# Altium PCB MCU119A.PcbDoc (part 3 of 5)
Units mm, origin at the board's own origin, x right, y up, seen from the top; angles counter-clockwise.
Board outline 58.62 x 144.37 mm, 6 copper layers (Top Signal, GND, Middle Signal, PWR, GND2, Bottom Signal), stack 1.566 mm thick; 316 components, 238 nets, 1210 pads, 1064 vias.
Unrouted connection lines stored in the file: 59.
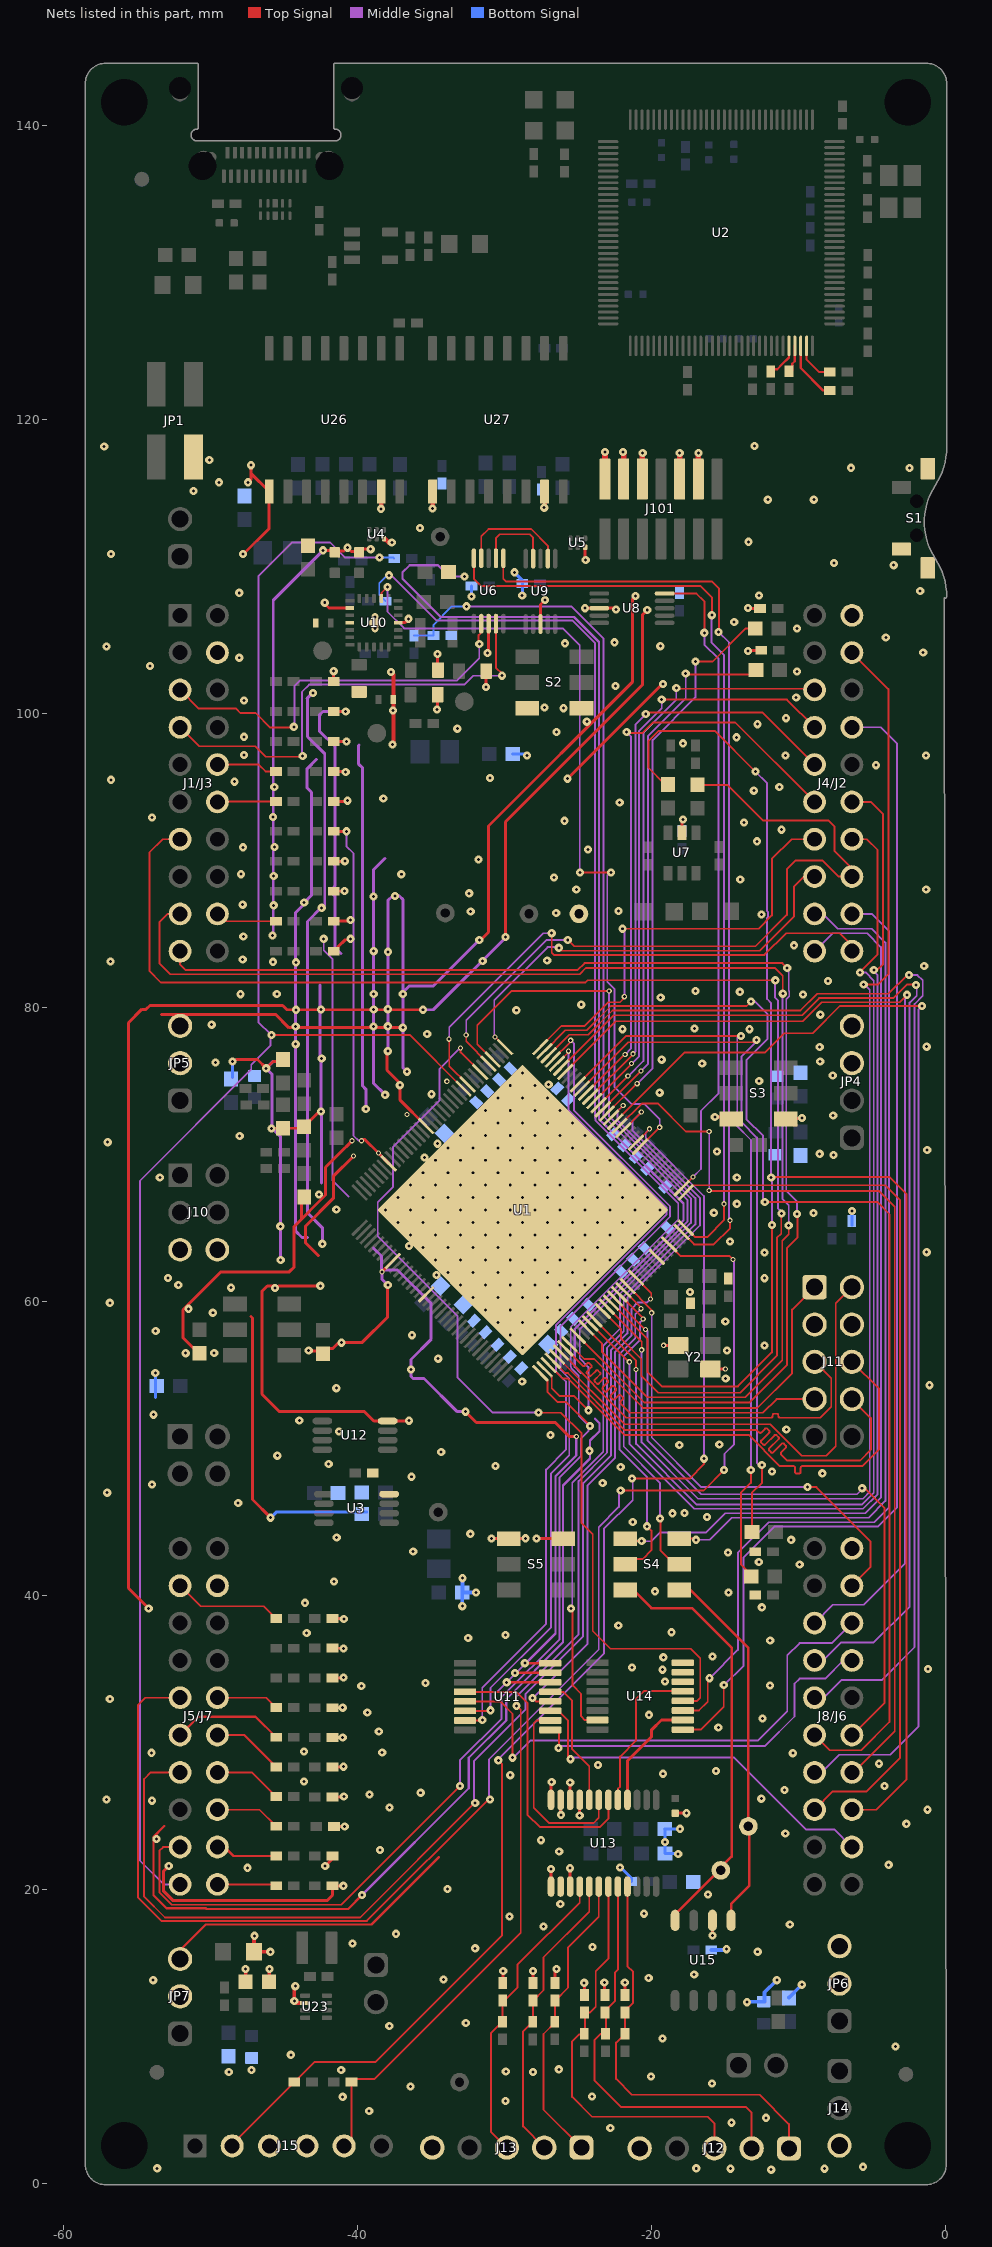
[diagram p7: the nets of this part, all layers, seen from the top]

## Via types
v1: diameter 0.559, hole 0.203, Top Signal to Bottom Signal, tented both sides, 833 vias
v2: diameter 0.5, hole 0.2, Top Signal to Bottom Signal, tented both sides, 146 vias
v3: diameter 0.356, hole 0.203, Top Signal to Bottom Signal, tented both sides, 83 vias
v4: diameter 0.4, hole 0.2, Top Signal to Bottom Signal, tented both sides, 2 vias

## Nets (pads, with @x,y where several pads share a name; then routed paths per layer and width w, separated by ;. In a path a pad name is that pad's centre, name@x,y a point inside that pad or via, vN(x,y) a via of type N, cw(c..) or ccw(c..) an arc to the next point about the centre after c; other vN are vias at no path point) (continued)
ADCINB9: J5/J7.67 R51.1 | length 4.7
  Top Signal w0.127: J5/J7.67@-49.521,27.96 -47.175,27.96 R51.1@-45.523,26.308
ADCINC0: J5/J7.68 R52.1 | length 4.5
  Top Signal w0.127: J5/J7.68@-49.521,25.42 -46.655,25.42 R52.1@-45.523,24.288
ADCINC1: J1/J3.29 R53.1 | length 4.2
  Top Signal w0.127: J1/J3.29@-49.521,86.38 -49.024,85.883 R53.1@-45.534,85.883
ADCINC2: J5/J7.42 R54.1 | length 7.5
  Top Signal w0.127: J5/J7.42@-52.061,40.66 -50.669,39.268 -46.362,39.268 R54.1@-45.523,38.43
ADCINC3: J5/J7.46 R55.1 | length 7.6
  Top Signal w0.152: J5/J7.46@-52.061,30.5 -50.811,31.75 -46.925,31.75 R55.1@-45.523,30.349
ADCINC8: J5/J7.66 R56.1 | length 4.9
  Top Signal w0.152: J5/J7.66@-49.521,30.5 -47.695,30.5 R56.1@-45.523,28.329
ADCIND1: J1/J3.25 R57.1 | length 4.2
  Top Signal w0.127: J1/J3.25@-49.521,96.54 -46.713,96.54 -46.248,96.075 R57.1@-45.534,96.075
ADCIND5: J5/J7.65 R58.1 | length 4.3
  Top Signal w0.127: J5/J7.65@-49.521,33.04 -46.194,33.04 R58.1@-45.523,32.369
ADCINE0/DACB_OUT: J5/J7.70 R60.1 | length 4
  Top Signal w0.127: J5/J7.70@-49.521,20.34 -45.616,20.34 R60.1@-45.523,20.247
ADCINE1: J5/J7.69 R61.1 | length 4.3
  Top Signal w0.152: J5/J7.69@-49.521,22.88 -49.042,22.88 -48.43,22.268 R61.1@-45.523,22.268
ADCINE7: J1/J3.26 R62.1 | length 4
  Top Signal w0.127: J1/J3.26@-49.521,94 -49.484,94.037 R62.1@-45.534,94.037
DEBUG_ID4: R101.1 U2.63 | length 2.9
  Top Signal w0.127: -9.426,124.102 -8.588,123.263 R101.1@-7.851,123.263
  Top Signal w0.152: -9.426,124.102 U2.63@-9.426,125.035
DEBUG_ID5: R102.1 U2.62 | length 4.1
  Top Signal w0.152: U2.62@-9.826,125.035 -9.826,123.522 -8.303,122 R102.1@-7.851,122
DEBUG_ID6: R103.1 U2.61 | length 2
  Top Signal w0.152: R103.1@-10.604,123.162 -10.405,123.362 -10.405,123.811 -10.235,123.981 -10.235,125.026 U2.61@-10.226,125.035
DEBUG_ID7: R104.1 U2.60 | length 2.5
  Top Signal w0.152: R104.1@-11.852,123.143 -11.852,123.232 -11.639,123.445 -11.424,123.445 -11.093,123.776 -10.626,124.243 U2.60@-10.626,125.035
EQEP1A: C6.1 J12.1 R5.1 U13.21 | length 28.4
  Top Signal w0.127: C6.1@-21.793,11.617 -21.793,11.735 -21.234,12.294 -21.234,14.376 -21.616,14.758 U13.21@-21.616,20.189 ; C6.1@-21.784,11.601 R5.1@-21.784,10.179 -22.389,9.574 -22.389,7.098 -21.311,6.02 -12.624,6.02 -10.624,4.02 J12.1@-10.624,2.368
EQEP1B: C7.1 J12.2 R6.1 U13.20 | length 28.1
  Top Signal w0.127: C7.1@-23.165,11.567 -23.089,11.49 -23.089,10.144 -23.46,10.144 -23.865,9.739 -23.865,6.999 -22.047,5.182 -13.538,5.182 -13.164,4.808 J12.2@-13.164,2.368 ; C7.1@-23.139,11.617 -23.139,11.735 -22.454,12.421 -22.454,14.351 -22.266,14.539 U13.20@-22.266,20.189
EQEP1I: C8.1 J12.3 R7.1 U13.19 | length 27.9
  Top Signal w0.127: U13.19@-22.916,20.189 -22.916,15.28 -23.774,14.422 -23.774,12.014 -24.171,11.617 -24.515,11.617 -24.515,10.146 -24.562,10.1 -24.572,10.11 -24.935,10.11 -25.38,9.665 -25.38,5.873 -24.028,4.521 -16.154,4.521 -15.704,4.071 J12.3@-15.704,2.368
EQEP2A: C9.1 J13.1 R8.1 U13.18 | length 20.4
  Top Signal w0.127: J13.1@-24.739,2.425 -27.33,5.017 -27.33,10.156 -26.543,10.943 C9.1@-26.543,12.43 -25.654,13.319 -25.654,16.053 -23.566,18.141 U13.18@-23.566,20.189
EQEP2B: C10.1 J13.2 R9.1 U13.17 | length 20.2
  Top Signal w0.127: J13.2@-27.279,2.425 -28.718,3.864 -28.718,10.338 R9.1@-28.067,10.989 -28.042,11.014 C10.1@-28.042,12.43 -27.33,13.141 -27.33,15.367 -24.216,18.481 U13.17@-24.216,20.189
EQEP2I: C11.1 J13.3 R10.1 U13.16 | length 20.7
  Top Signal w0.127: J13.3@-29.819,2.425 -30.912,3.518 -30.912,10.205 R10.1@-30.124,10.992 -30.124,12.29 -29.108,13.306 -29.108,14.859 -24.866,19.101 U13.16@-24.866,20.189
ERRORSTS: R26.2 R27.2 U1.74 | length 77.9
  Top Signal w0.127: U1.74@-27.259,55.403 -26.772,54.916 -26.772,54.109 -26.232,53.569 -25.243,53.569 v1(-24.274,52.6)
  Middle Signal w0.127: v1(-32.563,107.31) -25.446,107.31 -23.241,105.105 -23.241,72.593 -17.526,66.878 -17.526,65.467 -24.867,58.127 -24.867,56.134 -24.274,55.541 v1(-24.274,52.6)
  Bottom Signal w0.127: R26.2@-36.15,105.321 R27.2@-34.808,105.321 -34.808,106.061 -33.56,107.31 v1(-32.563,107.31)
GND: C1.2 C2.2 C3.2 C4.2 C5.1 C6.2 C7.2 C8.2 C9.2 C10.2 C11.2 C12.1 C13.2 C14.2 C15.2 C16.2 C17.1 C18.2 C19.2 C20.2 C21.2 C22.2 C23.2 C26.2 C27.2 C28.2 C29.1 C30.2 C31.2 C32.1 C33.2 C34.2 C35.2 C36.2 C37.2 C38.2 C39.2 C40.2 C41.1 C42.2 C43.2 C44.1 C45.2 C46.2 C47.2 C48.2 C49.2 C50.2 C51.2 C52.2 C53.2 C54.2 C55.2 C56.2 C57.2 C58.2 C59.2 C60.2 C61.2 C62.2 C63.2 C64.2 C65.2 C66.2 C67.2 C68.2 C69.2 C70.2 C71.2 C72.2 C73.2 C74.1 C75.1 C76.1 C77.2 C78.1 C79.2 C81.1 C82.2 C83.1 C84.2 C85.2 C86.1 C87.1 C88.1 C89.2 C90.2 C91.2 C92.2 C93.2 C94.2 C97.2 C98.2 C99.2 C100.2 C101.2 C102.2 C103.2 C104.2 C105.2 C106.2 C119.2 C120.2 C121.2 C130.2 C133.2 J1/J3.22 J4/J2.20 J5/J7.62 J8/J6.60 J10.5 J10.6 J11.3 J11.4 J12.5 J13.5 J14.3 J15.3 J15.4 J101.3 J101.5 J101.9 J101.11 J101.13 JP1.4 JP4.3 JP4.4 JP5.2 JP5.3 JP6.2 JP6.3 JP7.2 JP7.3 LED3.1 R27.1 R35.1 R36.2 S1.1 S1.2 S1.3 S2.3 S2.6 S3.1 S3.4 S5.1 S5.4 TP6.1 U1.20 U1.29 U1.45 U1.53 U1.101 U1.145 U3.4 U4.3 U5.3 U6.3 U7.2 U8.3 U9.3 U10. U10.2 U10.4 U10.16 U11.6 U11.7 U11.8 U12.4 U13.9 U13.10 U13.11 U13.12 U13.13 U13.14 U13.15 U14.6 U14.7 U14.8 U15.2 U23.6 U26.9 U26.15 U27.9 U27.15 Y2.2 Y2.4 | length 843.6
  Top Signal w0.152: -53.135,24.308 -53.873,23.569 -53.873,19.603 -52.977,18.707 -50.305,18.707 -50.267,18.669 -40.615,18.669 v1(-39.675,19.609) ; JP7.3@-52.061,15.26 -52.061,15.859 -50.305,17.615 -39.027,17.615 -34.437,22.205 ; v1(-29.835,34.091) U11.6@-26.869,34.091 ; v1(-29.261,34.722) -29.241,34.741 U11.7@-26.869,34.741 ; v1(-28.6,35.391) U11.8@-26.869,35.391
  Top Signal w0.203: v1(-54.194,39.114) -55.575,40.496 -55.575,78.969 -54.661,79.883 -54.378,79.883 -54.111,80.15 -45.076,80.15 -44.784,79.858 v1(-35.532,79.858) ; -53.315,79.527 -45.55,79.527 -44.661,78.638 v1(-36.906,78.638) ; v1(-52.832,21.59) -52.908,21.514 -53.2,21.222 -53.2,19.897 -52.531,19.228 -42.062,19.228 -41.691,19.599 C37.2@-41.691,20.244 ; C13.2@-50.724,56.476 -50.811,56.476 -51.867,57.531 -51.867,59.436 -49.276,62.027 -44.628,62.027 -44.298,62.357 -44.298,65.112 -42.164,67.246 -42.164,69.136 -40.855,70.446 -40.843,70.446 -40.724,70.565 -40.724,70.577 v3(-40.358,70.942) ; v1(-48.489,76.327) -48.392,76.327 -48.253,76.467 -46.799,76.467 v1(-46.203,75.87) -45.73,76.342 -45.193,76.342 C29.1@-45.069,76.467 ; v1(-47.778,110.871) -47.739,110.871 -45.996,112.614 U26.9@-45.996,115.118 -47.244,116.366 v1(-47.244,116.916) -47.244,115.951 v1(-47.447,115.748) ; -47.234,58.979 -47.14,58.885 -47.14,46.53 v1(-45.898,45.288) ; v1@-45.847,71.793 C41.1@-45.06,71.793 -43.739,71.793 C32.1@-43.637,71.895 -42.608,72.923 v1(-42.469,72.923) ; -43.805,65.633 -43.805,66.925 C44.1@-43.612,67.118 ; v1(-43.307,56.667) -43.231,56.667 -43.205,56.642 -42.532,56.642 C14.2@-42.342,56.452 -41.997,56.796 -41.687,56.796 -41.351,57.133 -41.14,57.133 v1(-41.072,57.201) -39.689,57.201 -37.935,58.955 -37.935,61.118 v1(-37.922,61.13) ; -42.647,63.119 -43.51,63.983 -43.51,65.145 -41.631,67.025 -41.631,68.52 v3(-40.25,69.901) ; v1(-42.52,61.072) -42.53,61.062 -45.363,61.062 -45.427,60.997 -45.527,60.997 -45.591,61.062 -46.126,61.062 -46.482,60.706 -46.482,53.696 -45.288,52.502 -39.507,52.502 -38.875,51.87 U12.4@-37.932,51.87 -36.497,51.87 v1(-36.474,51.892) ; v1@-42.22,111.078 -42.325,110.972 v1(-42.325,111.125) -41.667,111.125 C87.1@-41.529,110.987 -41.446,111.069 -40.899,111.069 v1(-40.665,111.303) -40.411,111.049 -39.94,111.049 C86.1@-39.878,110.987 -39.664,111.201 v1(-39.091,111.201) ; v1(-42.216,107.559) -42.216,107.494 -41.919,107.197 U10.2@-40.512,107.197 ; v1(-42.189,21.59) -41.589,22.19 C50.2@-41.589,22.276 ; C39.2@-41.606,83.844 -41.506,83.844 -41.307,84.042 -41.307,84.142 -40.828,84.621 -40.536,84.621 v1(-40.472,84.685) ; C34.2@-41.606,85.883 -40.654,85.883 -40.569,85.968 v1(-40.472,85.968) ; C30.2@-41.606,87.921 -40.882,87.921 v1(-40.869,87.935) ; C45.2@-41.606,89.96 -40.856,89.96 v1(-40.849,89.967) ; C40.2@-41.606,91.998 v1(-40.742,91.998) ; C38.2@-41.606,94.037 -40.71,94.037 v1(-40.665,94.082) ; C36.2@-41.606,96.075 -40.83,96.075 v1(-40.792,96.037) ; C27.2@-41.606,98.114 -41.599,98.12 v1(-40.742,98.12) ; C43.2@-41.606,100.152 v1(-40.792,100.152) ; C26.2@-41.606,102.191 v1@-41.606,102.895 ; C46.2@-41.595,24.268 v1(-40.857,24.268) ; C33.2@-41.595,26.291 -40.936,26.291 v1(-40.919,26.308) ; C48.2@-41.595,28.314 -40.977,28.314 v1(-40.945,28.346) ; C35.2@-41.595,30.337 -41.585,30.328 v1(-40.996,30.328) ; C49.2@-41.595,32.361 -41.594,32.36 v1(-40.996,32.36) ; C42.2@-41.595,34.384 -40.978,34.384 v1(-40.945,34.417) ; C31.2@-41.595,36.407 -40.953,36.407 v1(-40.945,36.398) ; C47.2@-41.595,38.43 -40.945,38.43 v1(-40.919,38.405) ; C37.2@-41.554,20.244 v1(-40.953,20.244) ; v3(-39.721,70.942) -39.645,71.018 -39.48,71.018 -38.566,70.104 v3(-38.557,70.104) -38.557,70.095 U1.29@-37.865,69.403 ; v3(-38.329,62.027) -38.312,62.027 U1.45@-37.582,62.757 ; v1(-37.922,77.038) -37.973,76.987 -37.973,75.743 -37.109,74.879 v1(-37.109,74.723) -37.109,73.739 U1.20@-35.32,71.949 ; U10.16@-37.212,106.197 -36.772,106.197 v1@-36.554,106.415 ; v1(-34.569,100.283) -34.533,100.319 C93.2@-34.533,101.168 ; v1(-34.544,104.064) -34.533,104.053 C94.2@-34.533,102.895 ; v1(-32.639,52.502) -31.902,51.765 -26.528,51.765 -25.583,50.82 v3(-25.095,50.82) ; v1(-31.699,84.607) -31.606,84.607 -31.077,85.136 -31.077,92.367 -21.26,102.184 -21.26,107.822 v1(-21.073,108.009) ; v1(-31.242,101.829) -31.231,101.839 C85.2@-31.231,102.904 ; v1(-31.14,104.14) -31.064,104.216 U6.3@-31.064,106.131 ; v1(-30.861,43.866) v1(-30.861,43.866) S5.1@-29.679,43.867 -28.574,43.867 v1(-28.55,43.891) ; C11.2@-30.099,13.63 -30.074,13.656 v1(-30.074,14.453) ; v1(-29.921,84.811) -29.921,92.644 -20.604,101.961 -20.604,106.726 v1(-20.269,107.061) ; C10.2@-28.042,13.63 v1(-28.042,14.453) ; v1(-27.813,43.866) v1(-27.813,43.866) S5.4@-25.979,43.867 ; U9.3@-27.534,106.106 -27.534,107.433 v1(-27.22,107.747) ; U13.13@-26.816,20.189 v1(-26.816,21.387) ; U13.12@-26.816,26.089 -26.816,27.27 v1(-26.772,27.314) ; C9.2@-26.543,13.63 -26.543,14.482 v1(-26.445,14.58) ; U13.11@-26.166,26.089 -26.166,25.099 v1(-26.137,25.07) ; v1(-25.695,95.583) -19.255,102.024 v1(-19.202,102.024) ; v1(-25.527,21.438) -25.516,21.427 U13.15@-25.516,20.189 ; U13.10@-25.516,26.089 v1(-25.516,27.27) ; v1(-24.866,25.019) U13.9@-24.866,26.089 ; v1(-24.562,13.64) -24.54,13.618 C8.2@-24.54,12.817 ; v1(-24.511,107.183) U8.3@-23.536,107.183 -22.483,107.183 v1(-22.397,107.097) ; U5.3@-24.494,111.333 -24.494,110.498 v1(-24.46,110.465) ; v1(-23.19,13.665) -23.19,12.868 C7.2@-23.139,12.817 ; C6.2@-21.793,12.817 v1(-21.793,13.665) ; v3(-19.152,57.023) -19.139,57.01 Y2.4@-18.169,57.01 ; C21.2@-18.364,25.179 v1(-17.602,25.179) ; U7.2@-17.905,91.9 -17.905,92.737 v1(-17.831,92.812) ; Y2.2@-15.969,55.41 v3(-14.956,55.41) ; v1(-15.831,16.866) U15.2@-15.831,17.889 ; v1(-15.672,72.568) -14.7,72.568 S3.4@-14.55,72.418 ; S3.4@-15.01,72.187 S3.4@-14.982,72.215 ; v1(-13.411,104.267) -13.36,104.318 C1.2@-12.513,104.318 ; v1(-13.411,107.188) -13.386,107.163 C2.2@-12.589,107.163 ; S3.1@-10.85,72.418 -10.411,72.418 -10.363,72.466 -9.855,72.466 v1@-9.779,72.39
  Top Signal w0.254: C121.2@-47.6,13.703 v1(-47.6,14.58) ; v1(-46.99,16.84) -47.032,16.798 LED3.1@-47.032,15.748 v1(-45.923,15.748) ; C120.2@-45.999,13.703 -45.999,14.554 v1(-45.974,14.58) ; v1(-44.221,13.411) -44.288,13.345 v1(-44.288,12.395) -44.157,12.264 U23.6@-43.552,12.264 ; v1(-37.705,102.845) -37.541,102.68 C90.2@-37.541,100.965 -37.541,97.969 v1(-37.602,97.907)
  Top Signal w0.305: v1(-38.391,113.949) -38.376,113.964 U26.15@-38.376,115.118 ; U4.3@-38.184,111.917 -38.13,111.917 -37.861,111.648 v1(-37.65,111.648) ; U27.9@-34.879,115.118 -34.879,113.974 v1(-34.874,113.97) ; v1(-27.28,114.021) -27.259,114.041 U27.15@-27.259,115.118
  Top Signal w0.381: J101.13@-23.144,115.973 v1(-23.144,117.805) ; v1(-21.92,117.805) -21.874,117.759 J101.11@-21.874,115.973 ; J101.9@-20.604,115.973 -20.604,117.731 v1(-20.581,117.754) ; J101.5@-18.064,115.973 -18.064,117.75 v1(-18.059,117.754) ; J101.3@-16.794,115.973 -16.794,117.75 v1(-16.789,117.754)
  Middle Signal w0.127: v1(-42.285,84.685) -42.285,83.901 -41.681,83.297 -41.681,68.232 -40.601,67.152 ; v1(-40.742,91.998) -40.742,90.983 -40.259,90.5 -40.259,71.289 -39.912,70.942 v3(-39.721,70.942)
  Middle Signal w0.152: v1(-39.675,19.609) -32.41,26.873 -32.41,28.956 -29.87,31.496 -29.87,32.943 -25.997,36.816 -25.997,47.489 -24.165,49.322 -24.165,50.537 -23.52,51.181 -23.52,51.714 -23.825,52.019 ; v1(-32.715,109.347) -33.748,109.347 -34.51,110.108 -36.44,110.108 -36.92,109.629 -36.92,109.184 -34.321,106.586 -25.255,106.586 -23.546,104.877 -23.546,72.409 -23.076,71.939 -23.066,71.93 -17.805,66.669 -17.805,65.529 -25.197,58.138 -25.197,55.561 -24.778,55.142 ; -30.48,33.452 -26.518,37.414 -26.518,48.108 -25.095,49.53 v3(-25.095,50.82)
  Middle Signal w0.203: v1(-45.847,71.78) v1@-45.822,71.806 ; -45.72,76.352 v1(-46.203,75.87) -45.822,75.489 v1@-45.822,71.806 ; v1@-45.72,84.861 v1(-45.771,84.912) -45.72,84.963 -45.72,107.73 v1(-42.325,111.125) ; v1(-45.212,62.827) -45.212,71.196 v1@-45.822,71.806 ; -43.383,64.364 -43.764,64.364 -44.221,64.821 -44.221,86.436 -43.612,87.046 v1(-43.612,87.147) -43.116,87.643 -43.116,94.653 -43.409,94.945 -43.409,96.266 -42.774,96.901 ; v1(-43.017,101.422) -43.037,101.422 -43.409,101.051 -43.383,101.026 -43.383,98.441 -42.216,97.274 -42.216,87 v1(-42.424,86.792) ; -42.545,81.553 -42.545,76.651 v1(-42.424,76.53) -42.494,76.46 -42.469,76.435 v1(-42.469,72.923) -42.447,72.901 -42.447,68.066 ; v1@-42.447,86.814 -43.396,85.865 -43.396,66.041 -42.382,65.028 v1(-42.382,63.932) ; -41.116,83.686 -41.516,84.087 -41.516,87.587 -41.572,87.643 -41.572,88.226 -41.516,88.282 -41.516,89.639 -41.553,89.675 -41.553,90.258 -41.516,90.295 -41.516,97.765 -42.583,98.831 -42.583,99.911 -42.342,100.152 v1(-40.792,100.152) ; -39.878,97.866 -39.903,97.841 -39.903,96.571 -39.637,96.304 -39.637,74.663 -39.421,74.447 v1(-39.421,73.101) ; -38.896,63.636 -38.354,63.094 v3@-38.354,62.154 ; v3(-38.557,70.104) -37.833,69.38 ; v3(-38.329,62.027) -38.329,61.537 v1(-37.922,61.13) ; v3@-38.252,62.154 -37.262,62.154 -34.976,59.868 -34.976,57.436 -36.347,56.064 -36.347,54.913 -36.206,54.771 -35.467,54.771 -33.198,52.502 v1(-32.639,52.502) ; -38.125,90.145 -38.91,89.36 -38.91,83.862 v1(-38.887,83.84) -38.91,83.817 -38.91,74.876 v1(-38.1,74.066) ; v1(-37.922,77.038) -37.922,87.291 -37.608,87.605 v1(-37.44,87.605) -37.135,87.605 -36.906,87.376 v1@-36.906,81.036 ; v1(-36.627,75.641) -36.906,75.921 v1(-36.906,78.638) -36.906,80.874 -36.987,80.955 v1@-36.906,81.036 ; v1(-35.532,79.858) -34.823,79.858 -29.921,84.76 v1(-29.921,84.811) ; v1(-31.699,84.607) -34.849,81.458 -36.484,81.458 v1@-36.906,81.036
  Bottom Signal w0.203: v1(-53.746,55.143) -53.734,55.131 -53.734,53.462 ; C77.2@-48.489,75.252 v1(-48.489,76.327) ; v1(-45.898,45.288) -45.517,45.669 C53.2@-39.358,45.669 ; v1@-32.223,107.965 v1(-32.223,107.98) ; v1@-32.223,107.965 C12.1@-32.223,108.687 ; C59.2@-29.423,97.257 -28.55,97.257 v1(-28.448,97.155) ; v1(-29.312,109.626) -28.769,109.083 C18.2@-28.769,108.864 -28.769,108.061 v1(-28.778,108.052) ; v1(-22.123,21.477) -22.084,21.438 -22.022,21.438 -21.352,20.768 C23.2@-21.352,20.523 ; v1(-18.161,22.403) -18.186,22.428 R36.2@-19.063,22.428 v1(-19.063,23.228) -19.063,24.094 R35.1@-19.088,24.119 v1(-18.034,24.119) ; C28.2@-6.35,65.192 -6.35,66.158 v1(-6.341,66.167)
  Bottom Signal w0.254: v1(-32.855,39.268) C60.2@-32.855,40.208 ; v1(-32.842,41.173) -32.842,40.221 C60.2@-32.855,40.208 ; v1(-31.926,40.208) C60.2@-32.855,40.208 ; C5.1@-15.917,15.875 -14.935,15.875 v1(-14.884,15.926) ; v1(-13.487,12.319) -13.449,12.358 -12.268,12.358 -12.283,12.373 -12.283,12.99 v1(-11.455,13.818) ; C84.2@-10.624,12.642 -10.611,12.642 -10.269,12.984 -10.269,12.997 v1(-9.754,13.513)
  other v1: -11.836,0.92 -14.605,0.991 -8.204,0.991 -53.619,1.016 -16.935,1.016 -5.588,1.118 -22.781,3.764 -14.526,4.119 -12.189,4.449 -39.193,4.907 -29.918,5.592 -40.995,5.881 -24.026,5.897 -36.374,6.584 -15.854,6.786 -20.012,7.269 -48.743,7.574 -28.039,7.574 -29.893,7.599 -47.193,7.703 -41.096,7.703 -26.286,7.751 -44.527,8.743 -3.378,9.296 -19.228,9.846 -37.821,10.699 -32.614,10.902 -53.889,13.818 -34.138,13.874 -20.168,13.975 -17.077,14.204 -12.752,15.753 -31.979,15.987 -24.004,16.083 -40.336,16.312 -37.364,16.972 -27.33,17.475 -10.567,17.607 -29.643,18.146 -20.499,18.344 -26.187,18.999 -16.13,19.639 -33.859,20.02 -47.473,21.463 -3.836,21.671 -26.264,22.581 -38.456,22.672 -27.508,23.343 -53.66,23.426 -10.871,23.803 -2.642,24.46 -1.199,25.42 -37.802,25.562 -53.974,26.032 -57.074,26.114 -12.51,26.167 -39.168,26.447 -35.688,26.574 -10.928,26.751 -4.115,27.04 -43.631,27.332 -29.592,27.767 -19.188,27.866 -15.596,28.061 -23.621,28.465 -4.496,28.55 -10.362,29.262 -54,29.293 -38.307,29.308 -43.631,29.388 -38.535,30.735 -15.433,31.017 -12.424,31.628 -20.158,31.879 -39.32,32.035 -56.845,32.944 -39.726,33.838 -11.913,33.878 -35.358,34.041 -19.068,34.138 -19.223,34.947 -1.168,34.986 -21.312,35.097 -19.178,35.793 -15.819,35.839 -11.903,36.934 -32.455,37.109 -29.91,37.313 -43.444,37.441 -18.621,37.496 -22.242,37.948 -12.471,39.192 -43.561,39.497 -14.732,40.208 -19.749,40.284 -41.581,40.95 -9.896,42.113 -12.675,42.282 -14.783,42.921 -36.196,42.982 -10.474,43.79 -41.403,43.947 -32.309,44.196 -21.256,45.007 -16.205,45.339 -18.542,45.593 -17.729,45.618 -48.108,46.284 -57.023,46.99 -53.976,47.556 -23.299,47.65 -36.304,48.077 -8.357,48.311 -11.786,48.438 -22.073,48.748 -30.604,48.811 -41.947,48.941 -45.441,49.51 -34.291,49.764 -24.207,49.84 -18.085,50.235 -15.368,50.268 -26.844,50.916 -41.255,51.157 -10.805,51.298 -43.946,51.911 -53.873,52.299 -41.427,54.106 -1.067,54.305 -28.778,54.559 -14.932,54.771 -36.347,55.383 -34.493,56.109 -51.68,56.489 -49.742,56.501 -14.838,56.662 -12.292,57.014 -36.271,57.709 -53.722,57.993 -14.956,58.641 -49.836,59.238 -51.481,59.503 -56.845,59.917 -17.364,60.658 -48.595,60.941 -45.591,60.929 -52.18,61.13 -52.883,61.595 -12.292,61.588 -34.62,61.798 -12.292,63.344 -1.249,63.358 -36.474,63.779 -14.646,64.087 -45.238,65.117 -15.739,66.042 -8.947,66.031 -41.427,66.269 -14.174,66.655 -42.602,67.294 -14.174,68.433 -53.438,68.446 -35.435,69.799 -7.585,69.979 -8.534,70.053 -15.519,70.219 -1.219,70.307 -34.544,70.739 -56.988,70.843 -48.006,71.272 -9.742,72.485 -7.615,72.663 -34.949,74.108 -19.422,74.212 -26.975,74.778 -12.649,75.006 -7.645,75.38 -16.531,76.205 -49.65,76.276 -8.501,76.327 -19.283,76.459 -8.533,77.323 -1.249,77.343 -44.19,77.511 -35.246,78.198 -21.955,78.537 -13.313,78.537 -17.047,78.588 -44.19,78.71 -38.893,78.71 -37.922,78.732 -49.911,78.842 -8.494,79.518 -29.18,79.823 -44.179,79.855 -42.479,79.877 -38.882,79.877 -37.922,79.898 -24.76,80.204 -19.351,80.692 -47.956,80.914 -9.661,80.89 -45.48,80.937 -38.887,80.924 -36.906,80.924 -13.97,81.077 -16.993,81.128 -7.976,81.822 -1.421,82.829 -44.168,83.088 -45.737,83.118 -56.794,83.134 -31.469,83.174 -27.077,83.206 -47.802,83.287 -37.917,83.803 -10.287,84.243 -47.761,84.841 -12.497,86.335 -26.467,86.436 -32.283,86.538 -22.226,86.568 -45.692,86.967 -47.802,87.007 -38.904,87.562 -32.385,87.784 -25.095,88.045 -1.29,88.045 -13.94,88.722 -26.619,88.849 -45.692,88.951 -47.905,89.083 -37.008,89.078 -31.75,90.092 -24.304,90.771 -47.778,90.912 -45.627,90.941 -12.795,91.323 -11.137,92.109 -13.678,92.6 -25.908,92.718 -53.973,92.939 -45.735,92.968 -22.143,93.968 -38.228,94.239 -13.02,94.767 -45.649,95.009 -11.285,95.021 -48.362,95.377 -56.769,95.504 -30.963,95.631 -4.705,96.497 -10.862,97.155 -1.304,97.155 -47.707,97.188 -17.83,97.99 -14.199,98.4 -47.719,98.43 -26.442,98.76 -33.198,98.984 -12.768,99.289 -24.379,99.459 -10.82,99.695 -37.567,100.228 -25.959,100.381 -27.254,100.432 -47.702,100.894 -10.134,101.099 -22.428,101.879 -10.087,102.872 -41.605,102.895 -54.102,103.251 -48.034,103.812 -1.49,104.16 -57.074,104.572 -19.38,104.597 -25.856,104.795 -22.495,104.859 -4.038,105.198 -10.087,105.793 -14.356,106.248 -36.519,106.459 -12.657,108.043 -48.034,108.228 -1.696,108.356 -3.496,110.111 -7.569,110.264 -56.769,110.871 -13.386,111.703 -35.738,112.649 -12.062,114.569 -8.937,114.569 -51.156,115.164 -49.403,115.748 -2.42,116.715 -6.401,116.738 -50.075,117.267 -57.224,118.188 -12.97,118.212
  other v2: -28.744,56.888 -29.592,57.736 -27.895,57.736 -30.441,58.585 -28.744,58.585 -27.046,58.585 -31.289,59.433 -29.592,59.433 -27.895,59.433 -26.198,59.433 -32.138,60.282 -30.441,60.282 -28.744,60.282 -27.046,60.282 -25.349,60.282 -32.986,61.13 -31.289,61.13 -29.592,61.13 -27.895,61.13 -26.198,61.13 -24.501,61.13 -33.835,61.979 -32.138,61.979 -30.441,61.979 -28.744,61.979 -27.046,61.979 -25.349,61.979 -23.652,61.979 -34.683,62.827 -32.986,62.827 -31.289,62.827 -29.592,62.827 -27.895,62.827 -26.198,62.827 -24.501,62.827 -22.804,62.827 -35.532,63.676 -33.835,63.676 -32.138,63.676 -30.441,63.676 -28.744,63.676 -27.046,63.676 -25.349,63.676 -23.652,63.676 -21.955,63.676 -36.38,64.524 -34.683,64.524 -32.986,64.524 -31.289,64.524 -29.592,64.524 -27.895,64.524 -26.198,64.524 -24.501,64.524 -22.804,64.524 -21.107,64.524 -37.229,65.373 -35.532,65.373 -33.835,65.373 -32.138,65.373 -30.441,65.373 -28.744,65.373 -27.046,65.373 -25.349,65.373 -23.652,65.373 -21.955,65.373 -20.258,65.373 -38.077,66.221 -36.38,66.221 -34.683,66.221 -32.986,66.221 -31.289,66.221 -29.592,66.221 -27.895,66.221 -26.198,66.221 -24.501,66.221 -22.804,66.221 -21.107,66.221 -19.41,66.221 -37.229,67.07 -35.532,67.07 -33.835,67.07 -32.138,67.07 -30.441,67.07 -28.744,67.07 -27.046,67.07 -25.349,67.07 -23.652,67.07 -21.955,67.07 -20.258,67.07 -36.38,67.918 -34.683,67.918 -32.986,67.918 -31.289,67.918 -29.592,67.918 -27.895,67.918 -26.198,67.918 -24.501,67.918 -22.804,67.918 -21.107,67.918 -35.532,68.767 -33.835,68.767 -32.138,68.767 -30.441,68.767 -28.744,68.767 -27.046,68.767 -25.349,68.767 -23.652,68.767 -21.955,68.767 -34.683,69.616 -32.986,69.616 -31.289,69.616 -29.592,69.616 -27.895,69.616 -26.198,69.616 -24.501,69.616 -22.804,69.616 -33.835,70.464 -32.138,70.464 -30.441,70.464 -28.744,70.464 -27.046,70.464 -25.349,70.464 -23.652,70.464 -32.986,71.313 -31.289,71.313 -29.592,71.313 -27.895,71.313 -26.198,71.313 -24.501,71.313 -32.138,72.161 -30.441,72.161 -28.744,72.161 -27.046,72.161 -25.349,72.161 -31.289,73.01 -29.592,73.01 -27.895,73.01 -26.198,73.01 -30.441,73.858 -28.744,73.858 -27.046,73.858 -29.592,74.707 -27.895,74.707 -28.744,75.555 -38.797,105.796 -38.797,106.598
  other v3: -36.61,72.722 -33.909,74.988
GPIO0: R1.2 U1.128 | length 38.4
  Top Signal w0.127: U1.128@-23.016,72.798 -20.985,74.828 v3(-20.955,74.828) ; v1(-16.993,103.556) -15.824,103.556 -13.589,105.791 R1.2@-12.916,105.791 ; R1.2@-12.916,105.699 R1.2@-12.779,105.699
  Middle Signal w0.127: v3(-20.955,74.828) -19.905,75.879 -19.905,98.205 -16.993,101.117 v1(-16.993,103.556)
GPIO1: R2.2 U1.129 | length 37.1
  Top Signal w0.127: U1.129@-23.299,73.08 -20.699,75.681 v3(-20.699,75.692) ; v1(-17.653,102.743) -17.729,102.667 -13.17,102.667 R2.2@-12.865,102.972
  Middle Signal w0.127: v3(-20.699,75.692) -20.691,75.692 -20.226,76.157 -20.226,98.468 -17.653,101.041 v1(-17.653,102.743)
GPIO2: J4/J2.38 U1.130 | length 40.3
  Top Signal w0.127: U1.130@-23.582,73.363 -21.602,75.343 v3(-21.595,75.343) ; v1(-18.292,101.757) -18.237,101.702 -9.409,101.702 -9.104,101.397 J4/J2.38@-8.881,101.62
  Middle Signal w0.127: v3(-21.595,75.343) -21.558,75.343 -20.532,76.369 -20.532,98.7 -18.292,100.939 v1(-18.292,101.757)
GPIO3: J4/J2.37 U1.131 | length 40.4
  Top Signal w0.127: U1.131@-23.865,73.646 -21.336,76.175 v3(-21.336,76.192) ; v1(-19.283,100.965) -10.766,100.965 J4/J2.37@-8.881,99.08
  Middle Signal w0.127: v3(-21.336,76.192) -20.828,76.7 -20.828,98.831 -19.283,100.376 v1(-19.283,100.965)
GPIO4: J4/J2.36 U1.132 | length 40.6
  Top Signal w0.127: U1.132@-24.147,73.929 -21.234,76.842 v3(-21.234,76.86) ; v1(-20.371,99.974) -20.269,100.076 -12.42,100.076 -8.884,96.54 J4/J2.36@-8.881,96.54
  Middle Signal w0.127: v3(-21.234,76.86) -21.057,77.038 -21.057,99.289 v1(-20.371,99.974)
GPIO5: J4/J2.35 U1.133 | length 41.3
  Top Signal w0.127: U1.133@-24.43,74.212 -21.832,76.81 v3(-21.768,76.81) ; v1(-21.666,98.755) -21.59,98.679 -20.596,98.679 -19.859,99.416 -14.297,99.416 J4/J2.35@-8.881,94
  Middle Signal w0.127: v3(-21.768,76.81) -21.378,77.2 -21.378,98.467 v1(-21.666,98.755)
GPIO6: R3.2 U1.134 | length 48.1
  Top Signal w0.127: U1.134@-24.713,74.495 -21.56,77.648 -14.308,77.648 -14.303,77.643 -12.984,77.643 v1(-12.827,77.8) ; R3.2@-13.144,44.323 -13.144,46.977 -12.471,47.65 v1(-12.471,48.87)
  Middle Signal w0.127: v1(-12.827,77.8) -12.827,77.699 -13.843,76.683 -13.843,72.203 -12.802,71.162 -12.802,49.022 -12.649,48.87 v1(-12.471,48.87)
GPIO7: R4.2 U1.135 | length 50.2
  Top Signal w0.127: U1.135@-24.996,74.777 -21.694,78.08 v1(-13.895,78.08) ; R4.2@-13.221,41.58 -13.36,41.58 -13.894,42.113 -13.894,46.99 -13.221,47.663 v1(-13.221,48.539)
  Middle Signal w0.127: v1(-13.895,78.08) -14.122,78.08 -14.148,78.054 -14.148,71.933 -13.208,70.993 -13.208,48.552 v1(-13.221,48.539)
GPIO8: J8/J6.78 U1.138 | length 72
  Top Signal w0.127: U1.138@-25.844,75.626 -22.4,79.07 -9.692,79.07 -8.397,80.366 -3.099,80.366 v1(-2.591,80.874)
  Middle Signal w0.127: J8/J6.78@-8.881,38.12 -7.631,39.37 -5.537,39.37 -2.718,42.189 -2.718,80.747 v1(-2.591,80.874)
GPIO9: J8/J6.77 U1.139 | length 77
  Top Signal w0.127: U1.139@-26.127,75.909 -22.549,79.487 -9.733,79.487 -8.576,80.645 -3.531,80.645 -2.591,81.585 -2.032,81.585 v1(-1.981,81.534)
  Middle Signal w0.127: J8/J6.77@-8.881,35.58 -8.286,35.58 -7.061,36.805 -4.851,36.805 -2.413,39.243 -2.413,80.34 -1.93,80.823 -1.93,81.483 v1(-1.981,81.534)
GPIO10: U1.140 U11.15 | length 56.4
  Top Signal w0.127: U11.15@-32.669,31.491 -31.526,31.491 v1(-31.496,31.521) ; U1.140@-26.41,76.192 -25.629,76.973 v3(-25.629,77.038)
  Middle Signal w0.127: v1(-31.496,31.521) -31.496,33.72 -27.153,38.064 -27.153,48.566 -25.806,49.912 -25.806,54.559 -26.467,55.22 -26.467,58.42 -18.948,65.938 -18.948,66.377 -25.629,73.057 v3(-25.629,77.038)
GPIO10_BP: J8/J6.57 U11.1 | length 25.6
  Top Signal w0.127: U11.1@-26.869,30.841 -26.371,30.841 -26.264,30.734 -26.264,29.591 v1@-26.314,29.54
  Middle Signal w0.127: v1(-26.314,29.616) -26.187,29.743 -12.268,29.743 -10.249,31.763 -10.249,33.998 -9.906,34.341 -8.153,34.341 -6.914,35.58 J8/J6.57@-6.341,35.58
GPIO10_Q2B: U11.2 U13.7 | length 13.2
  Top Signal w0.127: U11.2@-26.869,31.491 -27.792,31.491 -27.991,31.293 -27.991,25.557 -26.945,24.511 -23.927,24.511 -23.566,24.872 U13.7@-23.566,26.089
GPIO11: U1.141 U11.14 | length 57.5
  Top Signal w0.127: U11.14@-32.669,32.141 -30.978,32.141 v1(-30.937,32.182) ; U1.141@-26.693,76.474 -25.476,77.691 v3(-25.476,77.775)
  Middle Signal w0.127: v1(-30.937,32.182) -30.937,33.706 -26.816,37.827 -26.816,48.317 -25.578,49.555 -25.578,54.762 -26.162,55.347 -26.162,58.328 -18.72,65.77 -18.72,66.472 -25.248,73 -25.248,77.546 v3(-25.476,77.775)
GPIO11_BP: J8/J6.58 U11.13 | length 35.7
  Top Signal w0.127: U11.13@-32.669,32.791 -30.277,32.791 -29.439,31.953 v1(-29.439,28.956)
  Middle Signal w0.127: v1(-29.439,28.956) -29.388,28.956 -28.219,30.125 -12.75,30.125 -10.744,32.131 -10.744,35.916 -9.906,36.754 -7.707,36.754 J8/J6.58@-6.341,38.12
GPIO11_Q2A: U11.12 U13.6 | length 19.5
  Top Signal w0.127: U11.12@-32.669,33.441 -29.174,33.441 -28.423,32.69 -28.423,25.091 -27.564,24.232 -23.502,24.232 -22.916,24.817 U13.6@-22.916,26.089
GPIO12: J8/J6.76 U1.142 | length 81.7
  Top Signal w0.127: U1.142@-26.976,76.757 -25.577,78.156 -24.284,78.156 -22.633,79.807 -9.845,79.807 -8.702,80.95 -3.861,80.95 -2.591,82.22 v1(-2.464,82.22)
  Middle Signal w0.127: J8/J6.76@-8.881,33.04 -8.257,33.04 -7.058,34.239 -4.318,34.239 -2.083,36.474 -2.083,80.239 -1.524,80.797 -1.524,81.864 -1.88,82.22 v1(-2.464,82.22)
GPIO13: J8/J6.75 U1.143 | length 80.5
  Top Signal w0.127: U1.143@-27.259,77.04 -25.838,78.461 -24.387,78.461 -22.736,80.112 -13.513,80.112 v1(-13.208,80.416) ; v1(-12.268,66.777) -4.623,66.777 -3.785,65.938 -3.785,31.394 -5.715,29.464 -7.845,29.464 J8/J6.75@-8.881,30.5
  Middle Signal w0.127: v1(-13.208,80.416) -12.933,80.416 -12.09,79.573 -12.09,77.855 -13.517,76.428 -13.517,72.409 -12.386,71.277 -12.386,66.894 v1(-12.268,66.777)
GPIO14: J4/J2.34 U1.144 | length 29.7
  Top Signal w0.127: U1.144@-27.541,77.323 -26.105,78.76 -24.532,78.76 -22.926,80.366 -22.123,80.366 -21.828,80.661 v3(-21.828,80.747) ; v1(-21.955,85.369) -12.697,85.369 -11.786,86.281 -11.786,90.119 -10.445,91.46 J4/J2.34@-8.881,91.46
  Middle Signal w0.127: v1(-21.955,85.369) -21.828,85.242 v3(-21.828,80.747)
GPIO15: J4/J2.33 U1.1 | length 30.2
  Top Signal w0.127: v3(-30.632,78.003) -30.626,78.003 U1.1@-29.946,77.323 ; v1(-26.289,84.074) -26.086,83.871 -12.608,83.871 -10.287,86.192 -10.287,88.238 -9.605,88.92 J4/J2.33@-8.881,88.92
  Middle Signal w0.127: v3(-30.632,78.003) -30.683,78.054 -30.683,80.493 -27.051,84.125 -26.34,84.125 v1(-26.289,84.074)
GPIO17: U1.4 U14.15 | length 69.2
  Top Signal w0.127: U1.4@-30.794,76.474 -31.841,77.521 -31.841,78.802 -29.515,81.128 -23.98,81.128 v3(-22.86,81.128) ; v1(-25.451,39.116) -25.349,39.015 -25.349,33.878 -24.765,33.294 -24.765,31.775 -24.512,31.522 U14.15@-23.652,31.522
  Middle Signal w0.127: v1(-25.451,39.116) -25.375,39.192 -25.375,47.676 -23.266,49.784 -23.266,56.998 -22.123,58.141 -22.123,60.528 -17.297,65.354 -17.297,67.019 -21.742,71.464 -21.742,71.47 -22.53,72.257 -22.53,72.263 -22.86,72.593 v3(-22.86,81.128)
GPIO17_BP: J4/J2.17 U14.1 | length 81.5
  Top Signal w0.127: U14.1@-17.852,30.872 -16.626,30.872 -15.062,32.436 v1(-15.062,33.909)
  Middle Signal w0.127: v1(-15.062,33.909) -15.032,33.909 -13.716,35.225 -13.716,42.596 -11.608,44.704 -4.547,44.704 -3.277,45.974 -3.277,97.993 -4.363,99.08 J4/J2.17@-6.341,99.08
GPIO17_Q1B: U13.4 U14.2 | length 7.8
  Top Signal w0.2: U13.4@-21.616,26.089 -21.616,28.752 -19.965,30.403 -19.965,30.86 -19.303,31.522 U14.2@-17.852,31.522
GPIO18: J4/J2.11 U1.10 | length 37.2
  Top Signal w0.127: v3@-33.742,77.851 -33.742,76.028 U1.10@-32.491,74.777 ; v1(-26.772,85.065) -26.772,83.744 -26.619,83.591 -12.294,83.591 -10.82,85.065 -7.163,85.065 -6.341,84.243 J4/J2.11@-6.341,83.84
  Middle Signal w0.127: v3@-33.742,77.851 -33.742,78.679 -27.356,85.065 v1(-26.772,85.065)
  other v3: -33.757,77.851
GPIO19: J4/J2.13 R17.1 U1.5 | length 51.3
  Top Signal w0.127: v3(-32.588,78.13) -32.588,77.703 U1.5@-31.077,76.192 ; v1(-25.679,84.607) -25.248,84.176 -12.903,84.176 -10.77,86.309 -10.77,89.408 -10.16,90.018 -8.346,90.018 -7.248,88.92 J4/J2.13@-6.341,88.92 -6.341,89.475 -7.518,90.653 -7.518,92.304 -7.952,92.737 -12.397,92.737 -14.821,95.161 R17.1@-16.84,95.161
  Middle Signal w0.127: v3(-32.588,78.13) -32.588,79.137 -27.118,84.607 v1(-25.679,84.607)
GPIO22: J5/J7.50 R32.1 U1.11 | length 120.1
  Top Signal w0.127: v1(-45.847,78.13) -36.41,78.13 U1.11@-32.774,74.495
  Middle Signal w0.127: J5/J7.50@-52.061,20.34 -53.182,20.34 -54.788,21.946 -54.788,68.224 -47.219,75.794 -47.219,76.124 -45.898,77.445 v1@-45.898,78.181 ; v1(-45.847,78.13) v1@-45.898,78.181 ; v1(-38.481,110.642) -40.843,110.642 -41.859,111.658 -44.425,111.658 -46.736,109.347 -46.736,79.019 v1@-45.898,78.181
  Bottom Signal w0.127: v1(-38.481,110.642) -37.567,110.642 R32.1@-37.491,110.566
GPIO23: J15.5 R24.2 U1.127 | length 84.5
  Top Signal w0.127: J15.5@-40.396,3.089 -40.396,6.858 -40.278,6.858 -40.038,7.098 -38.825,7.098 -28.88,17.043 -28.88,32.207 v1(-29.159,32.487) ; U1.127@-22.733,72.515 v3(-21.906,73.341)
  Middle Signal w0.127: v1(-29.159,32.487) -29.185,32.512 -29.185,33.122 -24.943,37.363 -24.943,47.782 -23.008,49.717 -23.008,56.849 -21.869,57.988 -21.869,60.376 -16.993,65.253 -16.993,67.038 -21.514,71.559 -21.514,71.565 -22.301,72.352 -22.301,72.947 v3(-21.906,73.341)
GPIO24: J8/J6.74 U1.126 | length 82.5
  Top Signal w0.127: U1.126@-22.45,72.232 -17.746,76.937 -12.268,76.937 -10.947,78.257 -9.017,78.257 -7.163,80.112 v1(-1.575,80.112) ; J8/J6.74@-8.881,27.96 J8/J6.74@-8.195,27.96
  Middle Signal w0.127: J8/J6.74@-8.881,27.96 -8.387,27.96 -7.188,29.159 -3.734,29.159 -1.803,31.09 -1.803,79.883 v1(-1.575,80.112) v1@-1.575,80.273
GPIO25: J8/J6.54 U1.125 | length 64.4
  Top Signal w0.127: U1.125@-22.167,71.949 -20.647,73.47 -19.534,73.47 -17.633,71.568 v3(-16.053,71.568) ; v3(-16.053,67.564) -16.002,67.513 -4.496,67.513 -3.429,66.446 -3.429,30.759 -6.228,27.96 J8/J6.54@-6.341,27.96
  Middle Signal w0.127: v3(-16.053,67.564) v3(-16.053,71.568)
GPIO26: J5/J7.47 U1.124 | length 94.3
  Top Signal w0.127: J5/J7.47@-52.061,27.96 -54.057,27.96 -54.508,27.508 -54.508,19.507 -53.086,18.085 -39.802,18.085 -32.004,25.883 v1(-31.979,25.883) ; U1.124@-21.885,71.666 -20.673,72.878 v3(-20.673,72.907)
  Middle Signal w0.127: v1@-32.055,25.883 -32.055,28.753 -28.55,32.258 -28.55,33.299 -24.638,37.211 -24.638,47.65 -22.733,49.555 -22.733,56.718 -21.615,57.836 -21.615,60.249 -16.688,65.176 -16.688,67.056 -21.285,71.653 -21.285,72.263 -20.673,72.875 v3(-20.673,72.907)
GPIO29: J15.2 R23.1 U1.121 | length 90.6
  Top Signal w0.127: J15.2@-48.539,2.632 R23.1@-44.288,6.883 -42.912,8.259 -38.744,8.259 -30.159,16.845 -30.159,28.533 v1(-30.404,28.778) ; J15.2@-48.184,2.565 J15.2@-48.184,2.632 ; v1(-21.312,47.955) -17.388,47.955 -16.408,48.935 v1(-16.408,49.303) ; U1.121@-21.036,70.818 -20.117,71.737 v3(-20.117,71.755)
  Middle Signal w0.127: v1(-30.404,28.778) -30.404,28.854 -23.216,36.043 -23.216,44.526 -21.256,46.486 -21.256,47.899 v1(-21.312,47.955) ; v3(-20.117,71.755) -20.371,71.501 -20.371,71.145 -16.408,67.182 v1(-16.408,49.303)
GPIO30: U1.120 U10.21 | length 55.6
  Top Signal w0.127: U10.21@-38.362,107.847 -38.362,108.218 v1(-37.946,108.634) ; v1(-24.841,89.205) v1(-22.733,89.205) ; U1.120@-20.753,70.535 -19.431,71.857 v3(-19.422,71.857)
  Middle Signal w0.127: v1(-37.946,108.634) -37.946,106.946 -36.811,105.811 -26.004,105.811 -24.867,104.673 -24.867,89.23 v1(-24.841,89.205) ; v1(-22.733,89.205) -22.784,89.205 -22.987,89.002 -22.987,81.755 -22.504,81.272 -22.504,74.605 -21.335,73.435 -20.454,73.435 -19.422,72.403 v3(-19.422,71.857)
GPIO32: U1.96 U11.4 | length 34.1
  Top Signal w0.102: U1.96@-21.036,61.625 -19.99,60.579 -19.99,60.233 v3(-20.041,60.183)
  Top Signal w0.127: v1(-28.082,33.025) -27.849,32.791 U11.4@-26.869,32.791
  Middle Signal w0.127: v1(-28.082,33.025) -28.011,33.025 -24.333,36.703 -24.333,47.498 -22.454,49.378 -22.454,56.588 -21.336,57.706 -21.336,59.511 -20.903,59.944 -20.279,59.944 v3(-20.041,60.183)
GPIO32_BP: J8/J6.52 U11.3 | length 25.9
  Top Signal w0.127: U11.3@-26.869,32.141 -26.324,32.141 -25.654,31.471 -25.654,29.007 v1(-25.502,28.854)
  Middle Signal w0.127: v1(-25.502,28.854) -25.375,28.981 -14.376,28.981 -9.474,24.079 -7.54,24.079 J8/J6.52@-6.341,22.88
GPIO32_Q2I: U11.5 U13.8 | length 9
  Top Signal w0.127: U11.5@-26.869,33.441 -25.976,33.441 -25.38,32.845 -25.38,29.546 -24.216,28.382 U13.8@-24.216,26.089
GPIO34: U1.7 U14.4 | length 65
  Top Signal w0.127: v3(-32.976,77.256) -32.976,76.96 U1.7@-31.643,75.626 ; v1(-27.661,52.451) -27.64,52.43 -26.141,52.43 -24.736,51.025 -24.736,44.917 -23.978,44.159 -23.978,37.582 -22.769,36.373 -17.297,36.373 -16.662,35.738 -16.662,33.025 -16.865,32.822 U14.4@-17.852,32.822
  Middle Signal w0.127: v3(-32.976,77.256) -32.98,77.256 -34.402,75.834 -34.402,73.7 -37.567,70.536 -37.567,67.808 -38.608,66.767 -38.608,64.44 -33.172,59.004 -33.172,54.813 -30.81,52.451 v1(-27.661,52.451)
GPIO34_BP: J4/J2.12 U14.3 | length 66.7
  Top Signal w0.127: U14.3@-17.852,32.172 -16.748,32.172 -16.154,32.766 -16.154,34.236 v1(-16.024,34.366)
  Middle Signal w0.127: v1(-16.024,34.366) -14.097,36.293 -14.097,42.901 -12.014,44.983 -4.826,44.983 -3.81,45.999 -3.81,85.192 -4.998,86.38 J4/J2.12@-6.341,86.38
GPIO34_Q1I: U13.5 U14.5 | length 10.8
  Top Signal w0.127: U13.5@-22.266,26.089 -22.266,26.842 -22.118,26.99 -22.118,29.037 -21.036,30.12 -21.036,32.939 -20.472,33.503 -17.882,33.503 U14.5@-17.852,33.472
GPIO38: J5/J7.45 U1.104 | length 96
  Top Signal w0.127: J5/J7.45@-52.061,33.04 -54.438,33.04 -54.915,32.563 -54.915,19.431 -53.34,17.856 -39.345,17.856 -31.021,26.179 -30.978,26.136 v1(-30.978,26.114) ; v1(-22.073,47.142) -16.434,47.142 v1(-15.037,48.539) ; U1.104@-18.773,63.888 -17.979,63.094 -14.654,63.094 v3(-14.427,62.867)
  Middle Signal w0.127: v1(-30.978,26.114) -31.039,26.175 -31.039,28.854 -23.571,36.322 -23.571,44.653 -22.2,46.025 -22.2,47.016 v1(-22.073,47.142) ; v1(-15.037,48.539) -15.011,48.565 -15.011,49.646 -14.36,50.297 -14.36,62.8 v3(-14.427,62.867)
GPIO41: J5/J7.49 R29.1 U1.73 | length 139.2
  Top Signal w0.127: J5/J7.49@-52.061,22.88 -53.218,22.88 -53.467,22.631 -53.467,19.787 -52.629,18.948 -41.097,18.948 v1(-33.02,27.026) ; U1.73@-27.541,55.12 -27.046,54.625 -27.046,53.843 -26.365,53.162 -25.781,53.162 v1(-24.155,51.537)
  Middle Signal w0.127: v1@-37.616,109.347 -34.605,106.336 -25.346,106.336 -23.812,104.802 -23.812,72.501 -23.787,72.475 -23.787,72.309 -18.161,66.683 -18.161,65.583 -25.476,58.268 -25.476,55.553 -25.438,55.515 -25.438,55.461 -24.928,54.951 -24.928,52.22 -24.422,51.714 -24.333,51.714 v1(-24.155,51.537) -24.257,51.435 -24.257,51.206 -24.79,50.673 -24.79,49.482 -26.238,48.034 -26.238,37.033 -30.175,33.096 -30.175,31.623 -33.02,28.778 v1(-33.02,27.026)
  Bottom Signal w0.127: R29.1@-38.076,107.66 -38.506,108.09 -38.506,108.886 -37.969,109.423 v1(-37.846,109.423)
GPIO42: U1.107 U6.6 | length 64.3
  Top Signal w0.127: U6.6@-30.064,110.581 -30.064,109.185 -29.87,108.991 -15.85,108.991 -15.376,108.518 -15.376,105.604 v1(-15.418,105.562) ; U1.107@-17.925,64.737 -17.076,63.888 -15.741,63.888 -14.63,64.999 v3(-14.63,65.532)
  Middle Signal w0.127: v1(-15.418,105.562) -14.707,104.851 -14.707,66.794 -14.702,66.788 -14.702,66.511 -14.707,66.506 -14.707,65.608 v3(-14.63,65.532)
GPIO42_BP: J1/J3.4 U6.4 | length 31.2
  Top Signal w0.127: J1/J3.4@-52.061,99.08 -50.771,97.79 -46.939,97.79 -46.228,97.079 -43.764,97.079 v1(-43.713,97.13) ; U6.4@-30.564,105.956 -30.564,103.132 -30.15,102.718 v1(-30.15,102.591)
  Middle Signal w0.127: v1(-43.713,97.13) -43.764,97.18 -43.764,101.499 -43.282,101.981 -32.715,101.981 -32.106,102.591 v1(-30.15,102.591)
GPIO42_UARTTX: U6.7 U9.9 | length 5.5
  Top Signal w0.127: U6.7@-30.564,110.581 -30.564,111.947 -30.294,112.217 -28.27,112.217 -28.034,111.981 U9.9@-28.034,110.556
GPIO43: U1.108 U6.10 | length 64.2
  Top Signal w0.127: U6.10@-32.064,110.581 -32.064,109.187 -31.564,108.687 -16.637,108.687 -15.875,107.925 v1(-15.875,106.705) ; U1.108@-17.642,65.019 -17.012,64.389 -16.201,64.389 -15.037,65.553 v3(-15.037,66.65)
  Middle Signal w0.127: v1(-15.875,106.705) -15.9,106.68 -15.9,104.851 -15.037,103.988 v3(-15.037,66.65)
GPIO43_BP: J1/J3.3 U6.2 | length 27.5
  Top Signal w0.127: J1/J3.3@-52.061,101.62 -50.788,100.347 -48.251,100.347 -47.955,100.051 -46.914,100.051 -45.923,99.06 -44.374,99.06 v1(-44.323,99.111) ; v1(-31.699,104.75) -31.744,104.794 -31.744,105.35 -31.496,105.597 U6.2@-31.496,106.153
  Middle Signal w0.127: v1(-44.323,99.111) -44.272,99.162 -44.272,101.899 -43.911,102.26 -33.223,102.26 -31.699,103.784 v1(-31.699,104.75)
GPIO43_UARTRX: U6.9 U9.7 | length 7.6
  Top Signal w0.127: U6.9@-31.564,110.581 -31.564,112.069 -31.061,112.573 -28.173,112.573 -27.034,111.433 U9.7@-27.034,110.556
GPIO49_FSITXD0: J11.6 U1.75 | length 33.3
  Top Signal w0.127: U1.75@-26.976,55.686 -26.056,54.766 -25.673,54.766 -21.835,50.927 -13.361,50.927 -11.239,48.806 -10.781,48.806 -10.336,48.806 cw(c-10.336,48.679) -10.209,48.679 -10.209,48.399 ccw(c-10.114,48.399) -10.114,48.304 -9.923,48.304 ccw(c-9.923,48.399) -9.828,48.399 -9.828,48.679 cw(c-9.701,48.679) -9.701,48.806 -9.169,48.806 -5.627,48.806 -4.496,49.936 -4.496,54.055 J11.6@-6.341,55.9
GPIO50_FSITXD1: J11.8 U1.76 | length 33.6
  Top Signal w0.127: U1.76@-26.693,55.968 -25.861,55.137 -25.666,55.137 -21.786,51.257 -12.827,51.257 -12.717,51.148 -12.672,51.103 ccw(c-12.583,51.192) -12.493,51.103 -12.244,51.351 cw(c-12.177,51.284) -12.11,51.351 -11.975,51.217 cw(c-12.042,51.149) -11.975,51.082 -12.516,50.541 ccw(c-12.449,50.473) -12.516,50.406 -12.381,50.271 ccw(c-12.314,50.339) -12.247,50.271 -11.607,50.91 cw(c-11.54,50.843) -11.473,50.91 -11.338,50.776 cw(c-11.405,50.708) -11.338,50.641 -11.977,50.002 ccw(c-11.91,49.934) -11.977,49.867 -11.842,49.732 ccw(c-11.775,49.8) -11.708,49.732 -11.11,50.33 cw(c-11.043,50.263) -10.975,50.33 -10.841,50.196 cw(c-10.908,50.128) -10.841,50.061 -11.146,49.756 ccw(c-11.056,49.666) -11.146,49.576 -10.953,49.383 -10.908,49.338 -10.744,49.174 -5.791,49.174 -5.055,49.911 -5.055,52.074 J11.8@-6.341,53.36
GPIO51_FSITXCLK: J11.2 U1.77 | length 33.3
  Top Signal w0.127: U1.77@-26.41,56.251 -21.806,51.647 -11.886,51.647 -9.744,49.505 -8.103,49.505 -7.442,50.165 -7.442,59.879 J11.2@-6.341,60.98
GPIO52_FSIRXD0: J11.5 U1.78 | length 24.4
  Top Signal w0.127: U1.78@-26.127,56.534 -21.689,52.095 -11.924,52.095 -11.86,52.095 ccw(c-11.86,52.222) -11.733,52.222 -11.733,52.269 cw(c-11.638,52.269) -11.638,52.365 -11.447,52.365 cw(c-11.447,52.269) -11.352,52.269 -11.352,52.222 ccw(c-11.225,52.222) -11.225,52.095 -10.601,52.095 -8.484,52.095 -7.747,52.832 -7.747,54.766 J11.5@-8.881,55.9
GPIO53_FSIRXD1: J11.7 U1.79 | length 24.4
  Top Signal w0.127: U1.79@-25.844,56.817 -24.717,55.689 -24.672,55.645 ccw(c-24.582,55.734) -24.492,55.644 -24.341,55.795 cw(c-24.274,55.728) -24.207,55.795 -24.072,55.661 cw(c-24.139,55.593) -24.072,55.526 ; -24.072,55.526 -24.367,55.231 ccw(c-24.299,55.164) -24.367,55.097 -24.232,54.962 ccw(c-24.165,55.029) -24.097,54.962 -23.755,55.304 cw(c-23.687,55.237) -23.62,55.304 -23.485,55.17 cw(c-23.553,55.102) -23.485,55.035 -23.828,54.693 ccw(c-23.76,54.625) -23.828,54.558 -23.693,54.423 ccw(c-23.626,54.491) -23.558,54.423 -23.216,54.766 cw(c-23.149,54.698) -23.081,54.766 -22.947,54.631 cw(c-23.014,54.564) -22.947,54.496 -23.289,54.154 ccw(c-23.222,54.086) -23.289,54.019 -23.154,53.884 ccw(c-23.087,53.952) -23.02,53.884 -22.677,54.227 cw(c-22.61,54.159) -22.542,54.227 -22.408,54.092 cw(c-22.475,54.025) -22.408,53.957 -22.75,53.615 ccw(c-22.683,53.548) -22.75,53.48 -22.615,53.346 ccw(c-22.548,53.413) -22.481,53.346 -22.207,53.619 cw(c-22.14,53.552) -22.072,53.619 -21.938,53.485 cw(c-22.005,53.417) -21.938,53.35 -22.068,53.22 ccw(c-21.978,53.13) -22.068,53.04 -21.672,52.645 -21.627,52.6 -21.458,52.43 -12.399,52.43 -11.47,53.36 J11.7@-8.881,53.36
GPIO54_FSIRXCLK: J11.1 U1.80 | length 24.4
  Top Signal w0.127: U1.80@-25.562,57.1 -24.553,56.091 -23.889,56.091 -20.553,52.756 -12.786,52.756 -10.411,55.131 -10.411,59.45 J11.1@-8.881,60.98
GPIO56: J1/J3.10 U1.82 | length 87.7
  Top Signal w0.127: J1/J3.10@-52.061,83.84 -52.061,82.922 -51.689,82.55 -25.019,82.55 -24.536,83.033 -11.074,83.033 v1(-10.744,82.702) ; U1.82@-24.996,57.665 -20.455,53.125 -13.313,53.125 -10.754,55.684 -10.754,63.663 -10.033,64.384 -10.033,65.913 v1(-10.084,65.964)
  Middle Signal w0.127: v1(-10.744,82.702) -10.662,82.62 -10.662,82.431 -10.643,82.412 -10.643,81.166 -10.607,81.131 -10.607,80.769 -10.805,80.571 -10.805,67.549 -10.084,66.827 v1(-10.084,65.964)
GPIO57: J1/J3.9 U1.84 | length 90.8
  Top Signal w0.127: J1/J3.9@-52.061,86.38 -52.914,86.38 -53.457,85.836 -53.457,82.998 -52.732,82.272 -24.867,82.272 -24.437,82.702 -11.582,82.702 -11.044,82.164 v1(-11.044,80.95) ; U1.84@-24.43,58.231 -23.343,57.144 -23.343,56.551 -20.278,53.486 -13.613,53.486 -11.085,56.015 -11.085,64.15 -10.643,64.592 v1(-10.643,65.176)
  Middle Signal w0.127: v1(-11.044,80.95) -11.074,80.92 -11.074,66.98 -10.643,66.548 v1(-10.643,65.176)
GPIO58: J4/J2.15 U1.85 | length 77.7
  Top Signal w0.127: U1.85@-24.147,58.514 -21.533,55.9 v3(-21.488,55.9) ; J4/J2.15@-6.341,94 -5.049,94 -4.216,93.167 -4.216,82.956 -4.608,82.564 v1(-4.851,82.564)
  Middle Signal w0.127: v3(-21.488,55.9) -21.488,50.318 -17.068,45.898 -5.588,45.898 -4.592,46.894 -4.592,82.214 -4.851,82.474 v1(-4.851,82.564)
GPIO59: J4/J2.14 U1.86 | length 74.8
  Top Signal w0.127: U1.86@-23.865,58.797 -21.031,55.963 v3(-21.031,55.383) ; J4/J2.14@-6.341,91.46 -5.329,91.46 -4.597,90.729 -4.597,83.642 -5.787,82.452 v1(-5.787,82.398)
  Middle Signal w0.127: v3(-21.031,55.383) -21.031,50.317 -16.891,46.177 -5.664,46.177 -4.851,46.99 -4.851,81.834 -5.415,82.398 v1(-5.787,82.398)
GPIO60: J1/J3.7 U1.88 | length 95.7
  Top Signal w0.127: J1/J3.7@-52.061,91.46 -53.251,91.46 -54.153,90.559 -54.153,82.499 -53.365,81.712 -24.476,81.712 -24.324,81.864 v1(-11.557,81.864) ; U1.88@-23.299,59.362 -22.047,58.111 -22.047,57.466 -20.673,56.091 -20.673,54.938 -19.533,53.797 -13.955,53.797 -11.441,56.311 -11.441,64.327 -11.151,64.618 -11.151,65.964 v1(-11.125,65.989)
  Middle Signal w0.127: v1(-11.557,81.864) -11.582,81.839 -11.582,80.711 -11.379,80.508 -11.379,66.36 -11.125,66.106 v1(-11.125,65.989)
GPIO61: J4/J2.19 U1.89 | length 87.1
  Top Signal w0.127: U1.89@-23.016,59.645 -20.647,57.276 -20.647,56.722 v3(-20.65,56.718) ; J4/J2.19@-6.341,104.16 -3.861,101.68 -3.861,82.271 -4.547,81.585 v1(-5.537,81.585)
  Middle Signal w0.127: v3(-20.65,56.718) -20.65,50.419 -16.815,46.584 -5.588,46.584 -5.131,47.041 -5.131,81.229 -5.486,81.585 v1(-5.537,81.585)
GPIO62: J8/J6.53 R19.1 U1.90 | length 122.1
  Top Signal w0.127: U1.90@-22.733,59.928 -20.258,57.453 -20.258,55.218 -19.269,54.229 -14.099,54.229 -11.786,56.542 v1(-11.786,65.202) ; R19.1@-18.855,95.18 -19.031,95.18 -20.193,96.342 -20.193,98.12 -19.482,98.831 -15.672,98.831 v1(-12.903,96.063) ; v1(-11.836,68.433) -11.785,68.485 -3.791,68.485 -2.616,67.31 -2.616,27.483 -4.679,25.42 J8/J6.53@-6.341,25.42
  Middle Signal w0.127: v1(-12.903,96.063) -12.116,95.275 -12.116,86.571 -12.06,86.516 -12.06,86.154 -12.116,86.098 -12.116,80.59 -11.836,80.31 v1(-11.836,68.433) -11.786,68.382 v1(-11.786,65.202)
GPIO63: J8/J6.55 U1.91 | length 45.4
  Top Signal w0.127: U1.91@-22.45,60.211 -22.45,60.144 v3(-20.396,58.09) ; J8/J6.55@-6.341,30.5 -6.305,30.5 -4.115,32.69 -4.115,45.949 -5.461,47.295 v1(-5.639,47.295)
  Middle Signal w0.127: v3(-20.396,58.09) -20.332,58.09 -20.258,58.016 -20.258,50.56 -16.586,46.888 -5.994,46.888 -5.639,47.244 v1(-5.639,47.295)
GPIO64: S4.2 U1.92 | length 21.4
  Top Signal w0.102: U1.92@-22.167,60.494 -20.549,58.875 v3(-20.549,58.807)
  Top Signal w0.127: v1(-19.406,45.237) -19.369,45.201 -19.369,43.067 -18.419,42.117 S4.2@-18.075,42.117
  Middle Signal w0.127: v3(-20.549,58.807) -20.752,58.604 -20.752,57.404 -21.869,56.286 -21.869,50.135 -19.406,47.671 v1(-19.406,45.237)
GPIO64_BP: J4/J2.32 S4.3 | length 59.1
  Top Signal w0.127: S4.3@-17.825,43.617 S4.3@-18.075,43.867 -17.019,43.867 v1(-16.942,43.79)
  Middle Signal w0.127: v1(-16.942,43.79) -16.002,43.79 -14.503,45.288 -5.207,45.288 -4.064,46.431 -4.064,84.43 -5.004,85.369 -7.315,85.369 -8.326,86.38 J4/J2.32@-8.881,86.38
GPIO64_CANTX: S4.1 TP7.1 U15.1 | length 25.4
  Top Signal w0.178: S4.1@-18.075,40.367 -17.329,40.367 -13.408,36.445 -13.408,24.304 -13.335,24.232 -13.335,20.244 -14.561,19.017 U15.1@-14.561,17.889
GPIO65: S4.5 U1.93 | length 21.9
  Top Signal w0.102: U1.93@-21.885,60.777 -20.691,59.583 v3(-20.691,59.511)
  Top Signal w0.127: S4.5@-21.775,42.117 -21.414,42.478 -20.59,42.478 -19.99,43.078 -19.99,44.415 v1(-20.279,44.704)
  Middle Signal w0.127: v3(-20.691,59.511) -21.082,59.12 -21.082,57.506 -22.149,56.439 -22.149,49.911 -20.279,48.041 v1(-20.279,44.704)
GPIO65_BP: J4/J2.31 S4.6 | length 61.6
  Top Signal w0.127: S4.6@-21.775,43.867 -21.597,43.688 -21.571,43.714 v1(-20.65,43.714)
  Middle Signal w0.127: v1(-20.65,43.714) -20.624,43.688 -20.004,43.688 -19.42,44.272 -16.281,44.272 -14.961,45.593 -5.43,45.593 -4.363,46.66 -4.363,84.119 -5.309,85.065 -7.656,85.065 J4/J2.31@-8.881,83.84
GPIO65_CANRX: S4.4 TP8.1 U15.4 | length 29
  Top Signal w0.178: S4.4@-21.775,40.367 -21.217,40.367 -19.991,39.141 -17.221,39.141 -14.526,36.446 -14.526,22.233 -15.037,21.722 -15.037,21.615 -18.371,18.281 U15.4@-18.371,17.889
GPIO66: J8/J6.59 U1.94 | length 32.3
  Top Signal w0.102: U1.94@-21.602,61.06 -19.964,59.422 v3(-19.964,59.233)
  Top Signal w0.127: v1(-9.373,47.371) -8.763,47.371 -5.08,43.688 -5.08,41.921 J8/J6.59@-6.341,40.66
  Middle Signal w0.127: v3(-19.964,59.233) -19.964,50.749 -16.586,47.371 v1(-9.373,47.371)
GPIO68: J8/J6.73 U1.109 | length 60.4
  Top Signal w0.127: U1.109@-17.642,67.424 -17.147,67.918 -4.063,67.918 -3.073,66.929 -3.073,28.931 -5.334,26.67 -7.631,26.67 J8/J6.73@-8.881,25.42
GPIO70: U1.110 U8.10 | length 44.3
  Top Signal w0.127: U8.10@-19.086,108.183 -16.92,108.183 -16.385,107.647 v1(-16.385,105.512) ; U1.110@-17.925,67.706 v3(-17.147,68.485)
  Middle Signal w0.127: v3(-17.147,68.485) -16.612,69.02 -16.612,72.974 -15.418,74.168 -15.418,103.734 -16.385,104.701 v1(-16.385,105.512)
